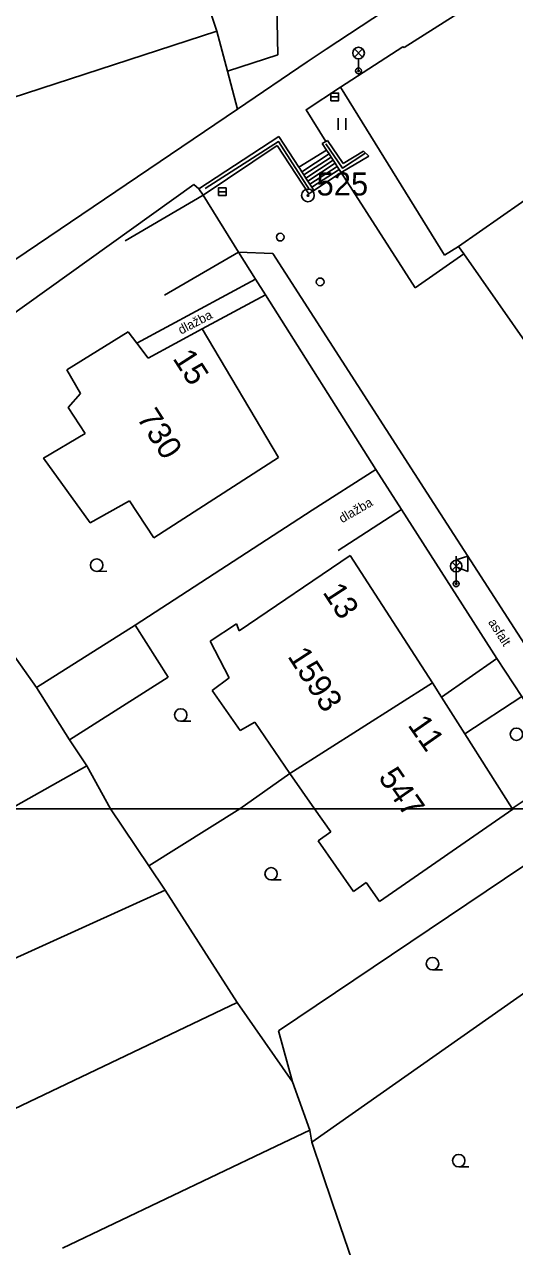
# Model space of a CAD drawing. Extents: x -493753 to -49290, y -1127285 to -112654.
# Drawn here: x -493092.4 to -493060.6, y -1127028.4 to -1126949.2 of the extents above; entities that cross this region are included whole.
import ezdxf

# ---------------------------------------------------------------- set-up
doc = ezdxf.new("R2010")
doc.units = 0
for name, color, linetype in [('Vrstva 10', 7, 'Continuous'), ('Vrstva 11', 7, 'Continuous'), ('Vrstva 27', 7, 'Continuous'), ('Vrstva 28', 7, 'Continuous'), ('Vrstva 31', 7, 'Continuous'), ('Vrstva 33', 7, 'Continuous'), ('Vrstva 36', 7, 'Continuous'), ('Vrstva 40', 7, 'Continuous'), ('Vrstva 43', 7, 'Continuous'), ('Vrstva 44', 7, 'Continuous'), ('Vrstva 5', 7, 'Continuous'), ('Vrstva 60', 7, 'Continuous'), ('Vrstva 63', 7, 'Continuous'), ('Vrstva 7', 7, 'Continuous'), ('Vrstva 8', 7, 'Continuous'), ('Vrstva 9', 7, 'Continuous')]:
    doc.layers.add(name, color=color, linetype=linetype)

msp = doc.modelspace()

# ---------------------------------------------------------------- linework, layer by layer
at = {"layer": 'Vrstva 10'}
for p, q in [((-493081.07, -1126959.81), (-493075.87, -1126956.42)), ((-493080.78, -1126960.24), (-493075.98, -1126957.01)), ((-493075.98, -1126957.01), (-493073.93, -1126960.15)), ((-493071.7, -1126958.17), (-493072.72, -1126956.69)), ((-493070.05, -1126957.7), (-493071.83, -1126958.77)), ((-493070.38, -1126957.37), (-493071.7, -1126958.17)), ((-493070.38, -1126957.37), (-493070.05, -1126957.7)), ((-493071.83, -1126958.77), (-493067.04, -1126966.23)), ((-493080.78, -1126960.24), (-493081.07, -1126959.81)), ((-493073.6, -1126959.93), (-493073.93, -1126960.15)), ((-493063.89, -1126964.03), (-493067.04, -1126966.23))]:
    msp.add_line(p, q, dxfattribs=at)
for points in [[(-493080.81, -1126920.54), (-493076.27, -1126935.1), (-493075.95, -1126951.13), (-493079.22, -1126952.19)], [(-493071.88, -1126953.24), (-493074.11, -1126954.7), (-493072.83, -1126956.75)], [(-493075.87, -1126956.42), (-493074.58, -1126958.42), (-493074.52, -1126958.51)], [(-493073.06, -1126956.88), (-493072.83, -1126956.75)], [(-493072.78, -1126957.32), (-493073.06, -1126956.88)], [(-493072.83, -1126956.75), (-493072.72, -1126956.69)], [(-493072.62, -1126957.56), (-493072.78, -1126957.32)], [(-493072.49, -1126957.76), (-493072.62, -1126957.56)], [(-493072.35, -1126957.96), (-493072.49, -1126957.76)], [(-493072.22, -1126958.16), (-493072.35, -1126957.96)], [(-493074.52, -1126958.51), (-493074.39, -1126958.71)], [(-493074.39, -1126958.71), (-493074.26, -1126958.92)], [(-493071.83, -1126958.77), (-493073.6, -1126959.93)], [(-493072.09, -1126958.37), (-493072.22, -1126958.16)], [(-493071.96, -1126958.57), (-493072.09, -1126958.37)], [(-493071.83, -1126958.77), (-493071.96, -1126958.57)], [(-493074.26, -1126958.92), (-493074.13, -1126959.12)], [(-493074.13, -1126959.12), (-493074, -1126959.32)], [(-493074, -1126959.32), (-493073.87, -1126959.52)], [(-493073.87, -1126959.52), (-493073.74, -1126959.72)], [(-493080.78, -1126960.24), (-493085.85, -1126963.18)], [(-493073.74, -1126959.72), (-493073.6, -1126959.93)], [(-493078.5, -1126963.93), (-493083.3, -1126966.72)], [(-493053.08, -1127000), (-493058.01, -1126992.34), (-493066.27, -1126979.55), (-493076.27, -1126964), (-493078.5, -1126963.93)], [(-493077.4, -1126965.67), (-493085.09, -1126969.83)], [(-493080.85, -1126968.9), (-493076.75, -1126966.68)], [(-493069.6, -1126978), (-493073.72, -1126980.65)], [(-493067.92, -1126980.61), (-493072.04, -1126983.26)], [(-493061.74, -1126990.26), (-493065.32, -1126992.77)], [(-493060.13, -1126992.71), (-493063.82, -1126995.14)], [(-493057.44, -1126997.77), (-493060.74, -1126999.98)]]:
    msp.add_lwpolyline(points, dxfattribs=at)
at = {"layer": 'Vrstva 11'}
for p, q in [((-493072.62, -1126957.56), (-493074.39, -1126958.71)), ((-493072.49, -1126957.76), (-493074.26, -1126958.92)), ((-493072.35, -1126957.96), (-493074.13, -1126959.12)), ((-493072.22, -1126958.16), (-493074, -1126959.32)), ((-493072.09, -1126958.37), (-493073.87, -1126959.52)), ((-493071.96, -1126958.57), (-493073.74, -1126959.72)), ((-493078.41, -1127000), (-493075.16, -1126997.71))]:
    msp.add_line(p, q, dxfattribs=at)
for points in [[(-493072.78, -1126957.32), (-493074.58, -1126958.42)], [(-493073.72, -1126980.65), (-493085.19, -1126988.1)], [(-493085.19, -1126988.1), (-493091.6, -1126992.14)], [(-493083.06, -1126991.47), (-493085.19, -1126988.1)], [(-493093.16, -1126989.93), (-493091.6, -1126992.14)], [(-493089.46, -1126995.52), (-493083.06, -1126991.47)], [(-493091.6, -1126992.14), (-493089.46, -1126995.52)], [(-493089.46, -1126995.52), (-493088.34, -1126997.22)], [(-493093.28, -1127000), (-493088.34, -1126997.22)], [(-493088.34, -1126997.22), (-493086.79, -1127000)], [(-493086.79, -1127000), (-493084.32, -1127003.7)], [(-493084.32, -1127003.7), (-493078.41, -1127000)], [(-493075.9, -1127014.38), (-493055.1, -1127000.4)], [(-493083.26, -1127005.28), (-493084.32, -1127003.7)], [(-493107.13, -1127016.09), (-493083.26, -1127005.28)], [(-493078.58, -1127012.54), (-493083.26, -1127005.28)], [(-493073.75, -1127021.61), (-493059.64, -1127011.71)], [(-493103.18, -1127024.29), (-493078.58, -1127012.54)], [(-493074.99, -1127017.7), (-493078.58, -1127012.54)], [(-493075.9, -1127014.38), (-493074.99, -1127017.7)], [(-493073.88, -1127020.83), (-493074.99, -1127017.7)], [(-493076.5, -1127022.08), (-493073.88, -1127020.83)], [(-493073.75, -1127021.61), (-493073.88, -1127020.83)], [(-493089.9, -1127028.48), (-493076.5, -1127022.08)], [(-493072.39, -1127025.58), (-493073.75, -1127021.61)], [(-493072.39, -1127025.58), (-493070.89, -1127029.99)]]:
    msp.add_lwpolyline(points, dxfattribs=at)
at = {"layer": 'Vrstva 27'}
for p, q in [((-493072.5, -1126953.86), (-493072, -1126953.86)), ((-493079.8, -1126960.01), (-493079.3, -1126960.01))]:
    msp.add_line(p, q, dxfattribs=at)
for points in [[(-493072.5, -1126954.11), (-493072, -1126954.11), (-493072, -1126953.61), (-493072.5, -1126953.61)], [(-493079.8, -1126960.26), (-493079.3, -1126960.26), (-493079.3, -1126959.76), (-493079.8, -1126959.76)]]:
    msp.add_lwpolyline(points, close=True, dxfattribs=at)
at = {"layer": 'Vrstva 28'}
msp.add_circle((-493073.2, -1126965.85), 0.25, dxfattribs=at)
at = {"layer": 'Vrstva 31'}
msp.add_circle((-493075.79, -1126962.95), 0.25, dxfattribs=at)
at = {"layer": 'Vrstva 33'}
for p, q in [((-493070.975, -1126950.755), (-493070.445, -1126951.285)), ((-493070.975, -1126951.285), (-493070.445, -1126950.755)), ((-493070.71, -1126952.17), (-493070.71, -1126951.395)), ((-493064.645, -1126984.005), (-493064.115, -1126984.535)), ((-493064.645, -1126984.535), (-493064.115, -1126984.005)), ((-493064.38, -1126983.62), (-493064.38, -1126985.37)), ((-493063.63, -1126983.62), (-493064.38, -1126983.87)), ((-493063.63, -1126983.62), (-493063.63, -1126984.62)), ((-493063.63, -1126984.62), (-493064.38, -1126984.32)), ((-493064.38, -1126985.42), (-493064.38, -1126984.645))]:
    msp.add_line(p, q, dxfattribs=at)
for centre, radius in [((-493070.71, -1126951.02), 0.375), ((-493070.71, -1126952.17), 0.19), ((-493070.71, -1126952.17), 0.05), ((-493064.38, -1126984.27), 0.375), ((-493064.38, -1126985.42), 0.19), ((-493064.38, -1126985.42), 0.05)]:
    msp.add_circle(centre, radius, dxfattribs=at)
at = {"layer": 'Vrstva 36'}
for p, q in [((-493072.03, -1126955.99), (-493072.03, -1126955.24)), ((-493071.53, -1126955.99), (-493071.53, -1126955.24)), ((-493087.692, -1126984.61), (-493087.042, -1126984.607)), ((-493082.242, -1126994.32), (-493081.592, -1126994.317)), ((-493076.382, -1127004.61), (-493075.732, -1127004.607)), ((-493065.912, -1127010.44), (-493065.262, -1127010.437)), ((-493064.212, -1127023.2), (-493063.562, -1127023.197))]:
    msp.add_line(p, q, dxfattribs=at)
for centre in [(-493087.692, -1126984.207), (-493082.242, -1126993.917), (-493060.472, -1126995.167), (-493076.382, -1127004.207), (-493065.912, -1127010.037), (-493064.212, -1127022.797)]:
    msp.add_circle(centre, 0.403, dxfattribs=at)
at = {"layer": 'Vrstva 5'}
for p, q in [((-493085.5, -1126932.37), (-493079.9, -1126949.6)), ((-493125, -1126964.26), (-493079.9, -1126949.6)), ((-493049.87, -1126953.52), (-493064.22, -1126963.55)), ((-493085.66, -1126969.08), (-493089.63, -1126971.55)), ((-493080.85, -1126968.9), (-493084.36, -1126970.8)), ((-493075.9, -1126977.24), (-493080.85, -1126968.9)), ((-493089.63, -1126971.55), (-493088.74, -1126973.08)), ((-493088.74, -1126973.08), (-493089.54, -1126974)), ((-493083.98, -1126982.43), (-493075.9, -1126977.24)), ((-493071.25, -1126983.58), (-493078.45, -1126988.46)), ((-493078.63, -1126988.01), (-493080.34, -1126989.13)), ((-493078.45, -1126988.46), (-493078.63, -1126988.01)), ((-493080.34, -1126989.13), (-493079.11, -1126991.51)), ((-493079.11, -1126991.51), (-493080.21, -1126992.33)), ((-493075.16, -1126997.71), (-493065.92, -1126991.83)), ((-493080.21, -1126992.33), (-493078.39, -1126994.93)), ((-493078.39, -1126994.93), (-493077.43, -1126994.39)), ((-493077.43, -1126994.39), (-493075.16, -1126997.71)), ((-493073.56, -1127000), (-493075.16, -1126997.71)), ((-493072.51, -1127001.5), (-493073.56, -1127000)), ((-493060.71, -1127000.02), (-493069.36, -1127006)), ((-493073.33, -1127002.07), (-493072.51, -1127001.5)), ((-493071.04, -1127005.35), (-493073.33, -1127002.07)), ((-493070.22, -1127004.77), (-493071.04, -1127005.35)), ((-493069.36, -1127006), (-493070.22, -1127004.77))]:
    msp.add_line(p, q, dxfattribs=at)
for points in [[(-493064.22, -1126963.55), (-493063.89, -1126964.03), (-493057.42, -1126973.28)], [(-493084.36, -1126970.8), (-493085.09, -1126969.83), (-493085.66, -1126969.08)], [(-493089.54, -1126974), (-493088.44, -1126975.67)], [(-493088.44, -1126975.67), (-493091.14, -1126977.27), (-493088.11, -1126981.46), (-493085.57, -1126980.03)], [(-493085.57, -1126980.03), (-493083.98, -1126982.43)], [(-493071.25, -1126983.58), (-493065.92, -1126991.83)], [(-493065.92, -1126991.83), (-493065.32, -1126992.77), (-493063.82, -1126995.14), (-493060.74, -1126999.98), (-493060.71, -1127000.02)]]:
    msp.add_lwpolyline(points, dxfattribs=at)
at = {"layer": 'Vrstva 60'}
for points in [[(-493125, -1126587.478), (-493125, -1127000), (-492991.121, -1127000)], [(-492991.121, -1127000), (-493125, -1127000), (-493125, -1127069.371)]]:
    msp.add_lwpolyline(points, dxfattribs=at)
at = {"layer": 'Vrstva 63'}
for radius in [0.412, 0.05]:
    msp.add_circle((-493073.99, -1126960.25), radius, dxfattribs=at)
at = {"layer": 'Vrstva 7'}
for p, q in [((-493067.75, -1126950.67), (-493048.63, -1126938.48)), ((-493081.4, -1126959.54), (-493081.07, -1126959.81)), ((-493080.78, -1126960.24), (-493078.5, -1126963.93)), ((-493065.14, -1126964.12), (-493064.22, -1126963.55))]:
    msp.add_line(p, q, dxfattribs=at)
for points in [[(-492984.63, -1126892.83), (-493007.99, -1126908.18), (-493072.81, -1126950.77)], [(-493079.9, -1126949.6), (-493079.22, -1126952.19), (-493078.57, -1126954.66)], [(-493071.88, -1126953.24), (-493067.84, -1126950.62), (-493067.75, -1126950.67)], [(-493074.04, -1126951.6), (-493078.57, -1126954.66), (-493106.67, -1126973.64), (-493125, -1126985.93)], [(-493065.14, -1126964.12), (-493071.88, -1126953.24)], [(-493103.04, -1126975.22), (-493103.07, -1126975.05), (-493081.4, -1126959.54)], [(-493078.5, -1126963.93), (-493077.4, -1126965.67), (-493076.75, -1126966.68), (-493069.6, -1126978)], [(-493067.92, -1126980.61), (-493061.74, -1126990.26), (-493060.13, -1126992.71), (-493057.58, -1126996.61)]]:
    msp.add_lwpolyline(points, dxfattribs=at)
at = {"layer": 'Vrstva 8'}
for points in [[(-493072.81, -1126950.77), (-493074.04, -1126951.6)], [(-493069.6, -1126978), (-493067.92, -1126980.61)]]:
    msp.add_lwpolyline(points, dxfattribs=at)
at = {"layer": 'Vrstva 9'}
for points in [[(-493073.89, -1126959.88), (-493075.9, -1126956.76), (-493080.65, -1126959.8)], [(-493070.31, -1126957.53), (-493071.76, -1126958.47), (-493072.83, -1126956.9)]]:
    msp.add_lwpolyline(points, dxfattribs=at)

# ---------------------------------------------------------------- texts
at = {"layer": 'Vrstva 40'}
for s, rotation, p in [('dlažba', 27.6716, (-493082.22, -1126969.274)), ('dlažba', 30.26501, (-493071.769, -1126981.5)), ('asfalt', 302.81016, (-493062.326, -1126987.909))]:
    msp.add_text(s, height=0.6, rotation=rotation, dxfattribs=at).set_placement(p)
at = {"layer": 'Vrstva 43'}
for s, rotation, p in [('730', 302.71372, (-493085.133, -1126974.661)), ('1593', 303.0261, (-493075.352, -1126990.114)), ('547', 304.95008, (-493069.475, -1126997.965))]:
    msp.add_text(s, height=1.5, rotation=rotation, dxfattribs=at).set_placement(p)
at = {"layer": 'Vrstva 44'}
for s, rotation, p in [('15', 302.71372, (-493082.801, -1126970.806)), ('13', 303.0261, (-493073.074, -1126985.962)), ('11', 304.95008, (-493067.56, -1126994.576))]:
    msp.add_text(s, height=1.5, rotation=rotation, dxfattribs=at).set_placement(p)
at = {"layer": 'Vrstva 63'}
msp.add_text(' 525', height=1.5, dxfattribs=at).set_placement((-493073.99, -1126960.25))

doc.saveas('drawing.dxf')
